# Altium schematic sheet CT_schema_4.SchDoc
size 283 x 147 mm
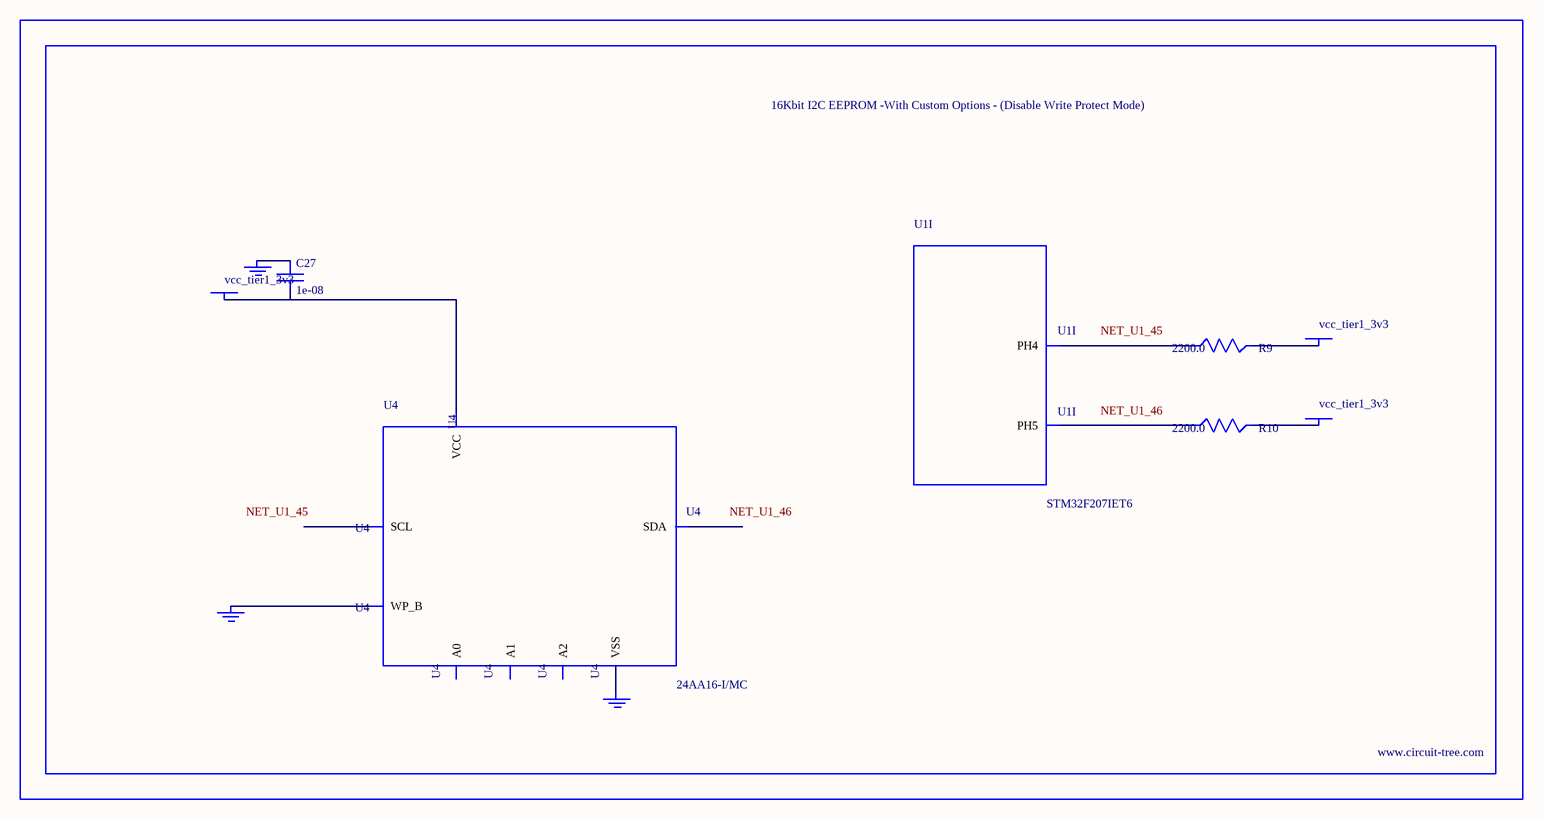
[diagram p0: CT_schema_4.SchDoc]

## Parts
BORDER3  (no value)
C27  1e-08  [C0402]
GND_INSTANCE_3_0  (no value)
GND_INSTANCE_3_1  (no value)
GND_INSTANCE_3_2  (no value)
POWER_INSTANCE_3_0  vcc_tier1_3v3
POWER_INSTANCE_3_1  vcc_tier1_3v3
POWER_INSTANCE_3_2  vcc_tier1_3v3
R9  2200.0  [R0603]
R10  2200.0  [R0603]
U1  STM32F207IET6  [LQFP176]  (part I of 11)
U4  24AA16-I/MC  [TDFN-8/6MM]

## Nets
NetC27_1: C27.1 GND_INSTANCE_3_1.0(GND)
NetC27_2: C27.2 POWER_INSTANCE_3_0.0(PWR) U4.8(VCC)
NetGND_INSTANCE_3_0_0: GND_INSTANCE_3_0.0(GND) U4.7(WP_B)
NetGND_INSTANCE_3_2_0: GND_INSTANCE_3_2.0(GND) U4.4(VSS)
NetPOWER_INSTANCE_3_1_0: POWER_INSTANCE_3_1.0(PWR) R9.2
NetPOWER_INSTANCE_3_2_0: POWER_INSTANCE_3_2.0(PWR) R10.2
NetR9_1: R9.1 U1.45(PH4)
NetR10_1: R10.1 U1.46(PH5)

Not connected (* = marked no-connect by the designer): U4 1(A0) 2(A1) 3(A2) 5(SDA) 6(SCL)

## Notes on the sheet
- Labels drawn without touching a wire or pin: NET_U1_45, NET_U1_46

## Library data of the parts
BORDER3 = BORDER_PAGE3
C27 = C0402C103K3RAC
GND_INSTANCE_3_0-GND_INSTANCE_3_2 = GND
POWER_INSTANCE_3_0-POWER_INSTANCE_3_2 = PWR
R9 R10 = RC0603JR-072K2L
